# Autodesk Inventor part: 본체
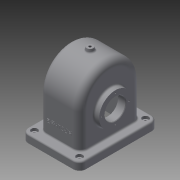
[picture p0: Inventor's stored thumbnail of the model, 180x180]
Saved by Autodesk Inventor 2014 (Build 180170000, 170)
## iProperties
Created: 2016-10
Part Number: 본체
Material: 일반
Document SubType Name: Modeling
Designer: USER
Density: 1 g/cm^3
Appearance: 기본값
Mass: 429.908 g
Surface Area: 1200.06 cm^2
Volume: 429.908 cm^3
Author: USER
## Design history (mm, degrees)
sketch "스케치1"
  geometry: L1 (-58, -65)-(-58, 0); L2 (58, 0)-(58, -65); L3 (58, -65)-(-58, -65); A1 r 58 centre (0, 0) between (58, 0) and (-58, 0); 1 further point
  constraints: 6 end point, 2 point on circle, 2 tangent, 1 centre point, 1 coincident, 1 parallel, 1 perpendicular, 1 vertical
  dimensions: "d0" = 65 distance from line of L3 point (0, 0); "d1" = 58 radius of A1; "d2" = 123 dimension on A1 L3
extrude "돌출1" new body sketch "스케치1" stored distance "d3" = 77; taper "d4" = 0 deg
node "작업 평면1"
sketch "스케치2"
  geometry: L1 (55, -75)-(-55, -75); L2 (-55, -75)-(-55, 75); L3 (-55, 75)-(55, 75); L4 (55, 75)-(55, -75); L5 (55, -75)-(-55, 75); L6 (-55, -75)-(55, 75); 1 further point
  constraints: 12 end point, 2 midpoint, 2 parallel, 1 horizontal, 1 perpendicular
  dimensions: "d6" = 110 distance of L2.end L3.end; "d7" = 150 distance of L1.end L2.end
extrude "돌출2" join sketch "스케치2" distance "d8" = 15; taper "d9" = 0 deg
sketch "스케치3"
  geometry: L1 (-58, -65)-(-58, 0) reference; L2 (-58, -65)-(-58, 0) reference; L3 (58, 0)-(58, -65) reference; L4 (58, -65)-(-58, -65) reference; L5 (52, -80)-(52, 0); L6 (-52, 0)-(-52, -80); L7 (-75, -80)-(75, -80) reference; L8 (-75, -80)-(-75, -65) reference; L9 (75, -65)-(-75, -65) reference; L10 (75, -80)-(75, -65) reference; A1 r 58 centre (0, 0) between (58, 0) and (-58, 0) reference; A2 r 58 centre (0, 0) between (58, 0) and (-58, 0) reference; A3 r 52 centre (0, 0) between (52, 0) and (-52, 0); 1 further point
  constraints: 4 end point, 2 point on circle, 2 point on line, 1 centre point
  dimensions: "d10" = 6 radial gap between concentric circles of A1 A3; "d11" = 6 distance between parallel lines of L1 L6; "d12" = 6 distance between parallel lines of L3 L5
extrude "돌출3" cut sketch "스케치3" stored distance "d13" = 67; taper "d14" = 0 deg
sketch "스케치4"
  geometry: L1 (80, 75)-(80, -75) reference; C1 r 31 at (15, 0); 1 further point
  constraints: 1 centre point, 1 horizontal alignment
  dimensions: "d15" = 62 diameter of C1; "d16" = 65 distance from line of L1 C1.centre
extrude "돌출4" join sketch "스케치4" distance "d17" = 10; taper "d18" = 0 deg
sketch "스케치5"
  geometry: L1 (-80, -75)-(-80, 75) reference; C1 r 37.5 at (-15, 0); 1 further point
  constraints: 1 centre point, 1 horizontal alignment
  dimensions: "d19" = 75 diameter of C1; "d20" = 65 distance from line of L1 C1.centre
extrude "돌출5" join sketch "스케치5" distance "d21" = 5; taper "d22" = 0 deg
hole "구멍1" diameter "d25" = 40; stored, may be unused: countersink angle "d29" = 90 deg, drill point angle "d31" = 118 deg; dims "d26" = 6, "d27" = 4, "d28" = 2, "d30" = 8, "d37" = 10, "d38" = 10
sketch "스케치6"
  geometry: L1 (33.5, -35)-(33.5, 5) reference; L2 (33.5, 24.747)-(33.5, -15); L3 (33.5, -15)-(19.5, -15); L4 (19.5, -15)-(19.5, 13); L5 (19.5, 13)-(33.5, 24.747); L6 (-33.5, -80)-(33.5, -80) reference; 1 further point
  constraints: 8 end point, 2 collinear, 1 parallel, 1 perpendicular
  dimensions: "d32" = 50 deg angle of L4 L5; "d33" = 14 distance between parallel lines of L4 L1; "d34" = 56 diameter of L4.end L3; "d35" = 65 distance between parallel lines of L6 L3
revolve "회전1" sketch "스케치6" stored, may be unused: angle "d36" = 90 deg
hole "구멍2" diameter "d41" = 40; stored, may be unused: countersink angle "d45" = 90 deg, drill point angle "d47" = 118 deg; dims "d39" = 10, "d40" = 10, "d42" = 6, "d43" = 4, "d44" = 2, "d46" = 8
node "작업 평면2"
sketch "스케치7"
  geometry: L1 (-38.5, 58)-(-38.5, -58) reference; C1 r 6 at (0, 0); 1 further point
  constraints: 1 centre point, 1 coincident
  dimensions: "d49" = 12 diameter of C1; "d50" = 38.5 distance from line of C1.centre L1
extrude "돌출6" join sketch "스케치7" stored distance "d51" = 5; taper "d52" = 10 deg
sketch "스케치8"
  geometry: C1 r 20 at (0, 0) reference; 2 further points
  constraints: 1 vertical alignment
  dimensions: "d53" = 26 distance of C1.centre point (0, 26)
hole "구멍3" sketch "스케치8" at (0, 26) diameter "d54" = 2.459; stored, may be unused: countersink angle "d58" = 90 deg, drill point angle "d60" = 118 deg; dims "d55" = 6, "d56" = 4, "d57" = 2, "d59" = 8
sketch "스케치9"
  geometry: C1 r 20 at (0, 0) reference; 2 further points
  constraints: 1 vertical alignment
  dimensions: "d64" = 29 distance of C1.centre point (0, 29)
hole "구멍4" sketch "스케치9" at (0, 29) diameter "d65" = 2.459; stored, may be unused: countersink angle "d69" = 90 deg, drill point angle "d71" = 118 deg; dims "d66" = 6, "d67" = 4, "d68" = 2, "d70" = 8
hole "구멍5" diameter "d77" = 4.459; stored, may be unused: countersink angle "d81" = 90 deg, drill point angle "d83" = 118 deg; dims "d75" = 10, "d76" = 10, "d78" = 6, "d79" = 4, "d80" = 2, "d82" = 8
chamfer "모따기1" distance "d84" = 1; stored, may be unused: second distance "d85" = 2, angle "d86" = 45 deg
fillet "모깎기1" dims "d87" = 3
fillet "모깎기2" dims "d88" = 13
fillet "모깎기3" dims "d89" = 3
fillet "모깎기4" dims "d90" = 8
fillet "모깎기5" dims "d91" = 12
fillet "모깎기6" dims "d92" = 3
sketch "스케치10"
  geometry: A1 r 9 centre (-43, 63) between (-43, 72) and (-52, 63) reference; 2 further points
  constraints: 1 coincident
hole "구멍6" sketch "스케치10" at (-43, 63) diameter "d93" = 5; stored, may be unused: countersink angle "d97" = 90 deg, drill point angle "d99" = 118 deg; dims "d94" = 6, "d95" = 12, "d96" = 5, "d98" = 8
fillet "모깎기7" dims "d100" = 3
node "작업 평면3"
sketch "스케치11"
  geometry: L1 (43, -80)-(-43, -80) reference; L2 (-38.5, 0)-(-38.5, -62) reference; 2 further points
  constraints: 1 other
  dimensions: "d102" = 40 distance from line of point (0, -40) L1; "d103" = 38.5 distance from line of point (0, -40) L2
feature "엠보싱1" sketch "스케치11" dims "d104" = 0.5, "d105" = 0
node "솔리드1"
pattern_circular "원형 패턴1" dims angle "d62" = 360 deg
pattern_circular "원형 패턴2" dims angle "d73" = 360 deg
mirror "대칭1"
mirror "대칭2"
node "투영된 루프1"
node "투영된 루프2"
other parameters: "d48" = 144
